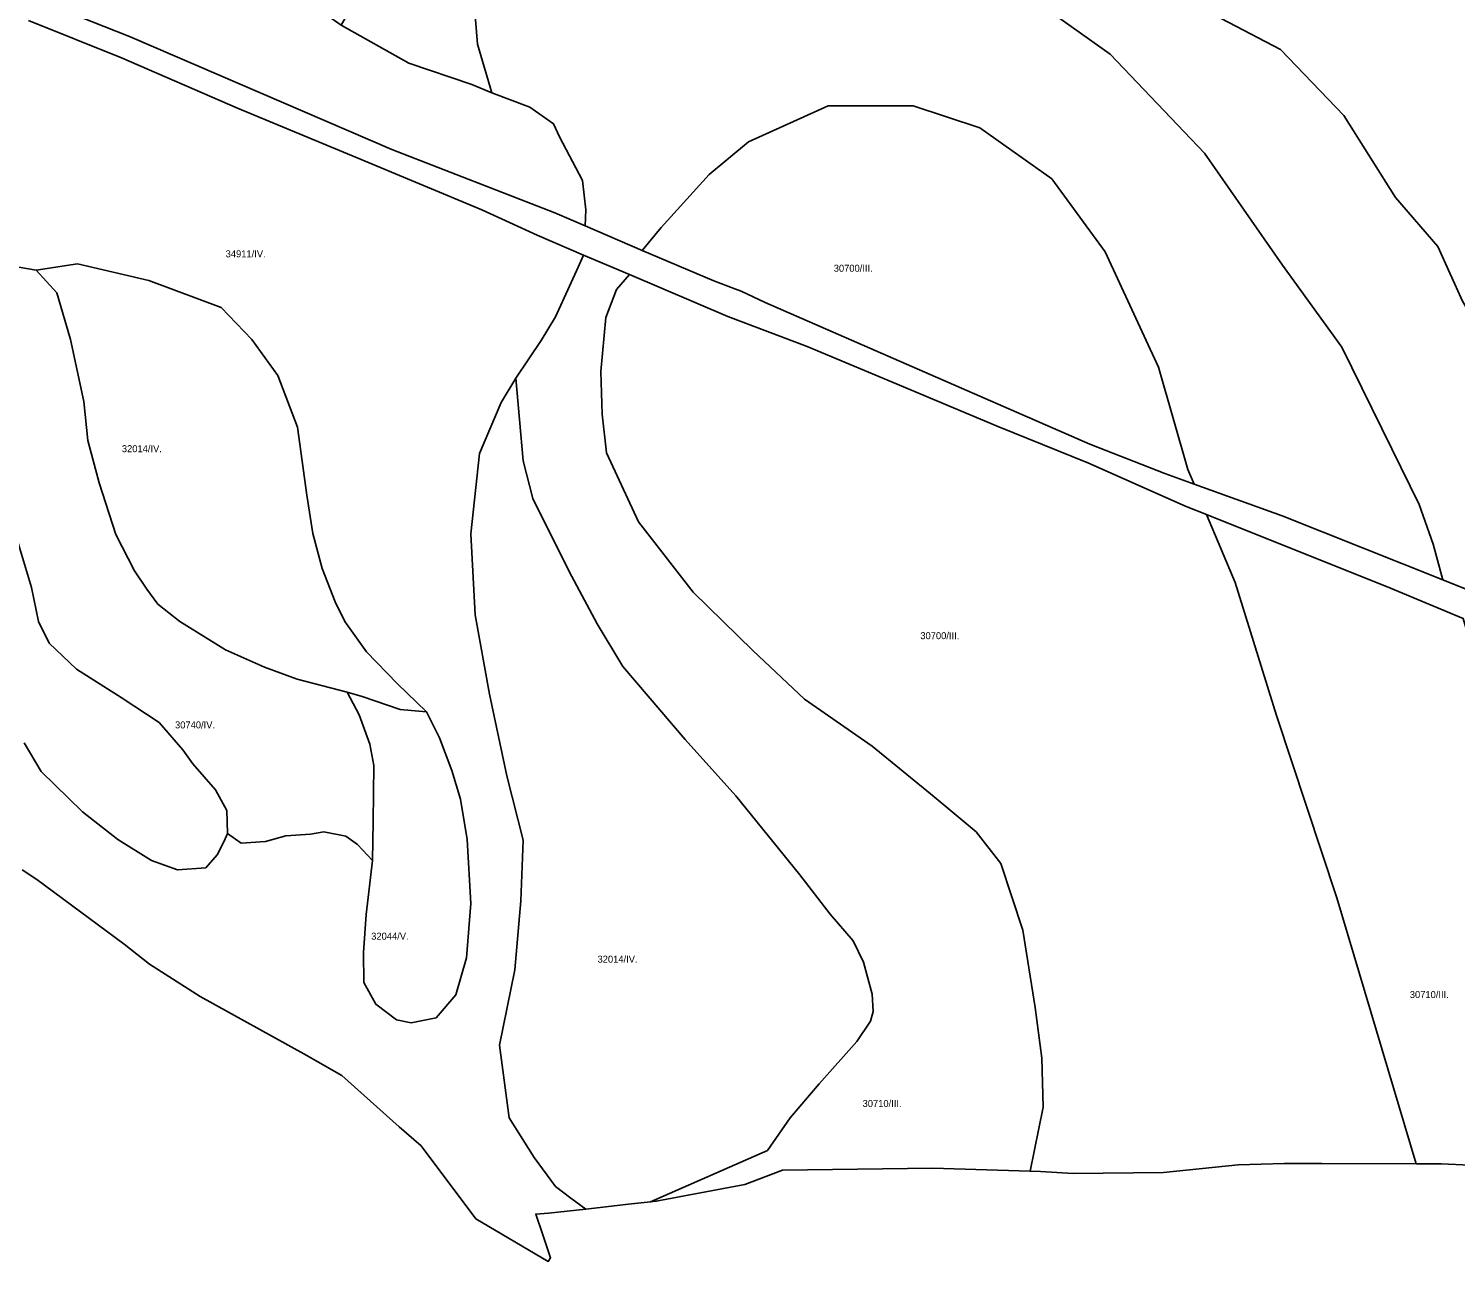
# Model space of a CAD drawing. Extents: x -521621 to -516761, y -1190184 to -1184927.
# Drawn here: x -520002 to -519186, y -1190057 to -1189352 of the extents above; entities that cross this region are included whole.
import ezdxf

# ---------------------------------------------------------------- set-up
doc = ezdxf.new("R2010")
doc.units = 0
doc.layers.add('BPEJ_s', color=7, linetype='Continuous')

msp = doc.modelspace()

# ---------------------------------------------------------------- linework, layer by layer
at = {"layer": 'BPEJ_s'}
for points in [[(-519823.1, -1189350.06), (-519806.14, -1189320.19), (-519800.04, -1189279.46), (-519787.14, -1189225.83), (-519785.79, -1189200.71), (-519787.14, -1189192.56), (-519745.76, -1189203.43), (-519719.98, -1189211.57), (-519700.98, -1189218.36), (-519715.91, -1189225.15), (-519729.48, -1189237.37), (-519742.37, -1189259.77), (-519747.12, -1189293.72), (-519747.79, -1189327.66), (-519745.08, -1189360.92), (-519736.94, -1189388.76), (-519748.47, -1189384), (-519784.43, -1189371.79)], [(-519650.89, -1189478.81), (-519640.16, -1189465.72), (-519612.7, -1189435.46), (-519590.11, -1189416.68), (-519544.58, -1189396.16), (-519495.92, -1189396.16), (-519457.69, -1189408.68), (-519416.67, -1189437.89), (-519386.09, -1189479.63), (-519355.5, -1189545.7), (-519338.82, -1189604.13), (-519335.14, -1189612.54), (-519351.91, -1189606.5), (-519394.82, -1189589.63), (-519580.62, -1189508.74), (-519594.34, -1189502.08), (-519597.85, -1189500.78), (-519609.99, -1189496.28)], [(-519997.55, -1189490.16), (-519973.93, -1189486.62), (-519933.2, -1189496.07), (-519891.87, -1189511.43), (-519874.16, -1189529.74), (-519859.4, -1189550.42), (-519848.18, -1189579.95), (-519842.87, -1189618.94), (-519839.33, -1189640.8), (-519834.02, -1189660.88), (-519826.6, -1189679.9), (-519821.01, -1189691.1), (-519808.57, -1189708.52), (-519791.17, -1189726.56), (-519774.38, -1189742.73), (-519789.3, -1189741.49), (-519811.06, -1189734.02), (-519819.76, -1189731.53), (-519848.36, -1189724.07), (-519867.01, -1189717.23), (-519889.39, -1189707.27), (-519915.5, -1189691.1), (-519927.93, -1189681.15), (-519934.38, -1189672.7), (-519941.46, -1189662.06), (-519952.09, -1189641.39), (-519961.54, -1189611.85), (-519968.03, -1189587.63), (-519970.39, -1189565.19), (-519978.07, -1189529.74), (-519985.74, -1189503.16)], [(-519723.22, -1189551.96), (-519708.63, -1189530.4), (-519700.59, -1189516.75), (-519687.6, -1189488.39), (-519684.5, -1189481.48), (-519658.23, -1189492.66), (-519665.53, -1189501.19), (-519671.78, -1189517.19), (-519674.57, -1189548.14), (-519673.87, -1189572.48), (-519671.44, -1189594.74), (-519653.02, -1189634.04), (-519621.74, -1189674.38), (-519587.67, -1189707.77), (-519558.08, -1189735.65), (-519519.34, -1189762.4), (-519483.87, -1189791.34), (-519459.87, -1189811.54), (-519445.68, -1189829.55), (-519433.13, -1189867.77), (-519426.04, -1189911.99), (-519422.22, -1189940.93), (-519421.46, -1189968.96), (-519429, -1190005.61), (-519484.81, -1190003.91), (-519570.62, -1190005.01), (-519592.2, -1190013.2), (-519642.88, -1190022.74), (-519646.24, -1190023.11), (-519579.27, -1189993.71), (-519566.27, -1189975.04), (-519549.69, -1189955.68), (-519528.13, -1189931.35), (-519520.4, -1189919.74), (-519518.74, -1189914.21), (-519519.29, -1189904.25), (-519524.26, -1189886), (-519530.25, -1189873.77), (-519543.35, -1189858.49), (-519560.81, -1189836.1), (-519597.36, -1189790.79), (-519626.28, -1189758.58), (-519662.05, -1189716.81), (-519676.65, -1189692.47), (-519692.64, -1189662.56), (-519713.49, -1189620.82), (-519719.05, -1189599.26)], [(-519658.23, -1189492.66), (-519601.94, -1189516.62), (-519556.54, -1189533.86), (-519507.3, -1189554.4), (-519447.8, -1189579.47), (-519395.97, -1189600.37), (-519339.66, -1189625.28), (-519328.03, -1189629.94), (-519311.71, -1189668.82), (-519288, -1189744.93), (-519253.62, -1189849.21), (-519208.1, -1190001.4), (-519262.12, -1190001.22), (-519283.62, -1190001.22), (-519309.98, -1190002.04), (-519352.75, -1190006.3), (-519404.45, -1190006.91), (-519423.04, -1190005.79), (-519429, -1190005.61), (-519421.46, -1189968.96), (-519422.22, -1189940.93), (-519426.04, -1189911.99), (-519433.13, -1189867.77), (-519445.68, -1189829.55), (-519459.87, -1189811.54), (-519483.87, -1189791.34), (-519519.34, -1189762.4), (-519558.08, -1189735.65), (-519587.67, -1189707.77), (-519621.74, -1189674.38), (-519653.02, -1189634.04), (-519671.44, -1189594.74), (-519673.87, -1189572.48), (-519674.57, -1189548.14), (-519671.78, -1189517.19), (-519665.53, -1189501.19)], [(-519723.22, -1189551.96), (-519719.05, -1189599.26), (-519713.49, -1189620.82), (-519692.64, -1189662.56), (-519676.65, -1189692.47), (-519662.05, -1189716.81), (-519626.28, -1189758.58), (-519597.36, -1189790.79), (-519560.81, -1189836.1), (-519543.35, -1189858.49), (-519530.25, -1189873.77), (-519524.26, -1189886), (-519519.29, -1189904.25), (-519518.74, -1189914.21), (-519520.4, -1189919.74), (-519528.13, -1189931.35), (-519549.69, -1189955.68), (-519566.27, -1189975.04), (-519579.27, -1189993.71), (-519646.24, -1190023.11), (-519658.79, -1190024.51), (-519683.22, -1190027.22), (-519691.73, -1190020.94), (-519700.58, -1190014.31), (-519712.74, -1189997.72), (-519727.11, -1189975.04), (-519732.63, -1189933.56), (-519723.79, -1189890.43), (-519720.3, -1189850.97), (-519719.05, -1189816.13), (-519728.38, -1189779.43), (-519738.33, -1189732.78), (-519746.41, -1189687.37), (-519748.94, -1189641), (-519744.08, -1189595.09), (-519731.57, -1189565.88)], [(-519208.1, -1190001.4), (-519253.62, -1189849.21), (-519288, -1189744.93), (-519311.71, -1189668.82), (-519328.03, -1189629.94), (-519222.81, -1189672.05), (-519181.35, -1189689.34), (-519166.46, -1189740.01), (-519153.87, -1189796.77), (-519138.14, -1189844.98), (-519114.04, -1189889.74), (-519082.58, -1189926.64), (-519049.15, -1189950.75), (-519010.3, -1189966), (-518966.06, -1189982.72), (-518939.67, -1189985.22), (-518959.14, -1189990.09), (-519013.06, -1189993.13), (-519106.78, -1190001.04), (-519141.44, -1190003.47), (-519150.16, -1190003.47), (-519160.74, -1190002.98), (-519193.76, -1190001.45)], [(-519819.76, -1189731.53), (-519811.06, -1189734.02), (-519789.3, -1189741.49), (-519774.38, -1189742.73), (-519766.92, -1189757.66), (-519759.77, -1189776.32), (-519754.8, -1189792.81), (-519751.07, -1189815.82), (-519748.89, -1189852.52), (-519751.38, -1189883.62), (-519757.6, -1189904.77), (-519768.79, -1189917.84), (-519783.09, -1189920.64), (-519791.48, -1189919.08), (-519803.29, -1189910.06), (-519810.13, -1189897.62), (-519810.44, -1189880.52), (-519808.88, -1189858.74), (-519805.15, -1189827.95), (-519804.84, -1189805.56), (-519804.53, -1189773.52), (-519806.71, -1189761.39), (-519812.93, -1189744.6)]]:
    msp.add_lwpolyline(points, close=True, dxfattribs=at)
for points in [[(-520006.99, -1189287.86), (-519999.5, -1189292.36), (-519964.22, -1189295.07), (-519909.27, -1189314.08), (-519860.42, -1189329.7), (-519832.6, -1189343.27), (-519823.1, -1189350.06), (-519784.43, -1189371.79), (-519748.47, -1189384), (-519736.94, -1189388.76), (-519715.23, -1189396.9), (-519701.66, -1189406.41), (-519698.2, -1189413.9), (-519684.99, -1189438.94), (-519683.25, -1189455.63), (-519683.56, -1189464.86), (-519700.98, -1189457.42), (-519794.24, -1189421.2), (-519944.22, -1189356.48), (-519993.99, -1189336.93), (-520071.75, -1189303.77)], [(-519421.98, -1189339.11), (-519383.19, -1189366.6), (-519329.33, -1189423.2), (-519284.62, -1189487.34), (-519250.68, -1189534.23), (-519222.13, -1189592.45), (-519206.51, -1189624.25), (-519198.41, -1189646.81), (-519192.94, -1189667.39), (-519284.87, -1189630.65), (-519335.14, -1189612.54), (-519338.82, -1189604.13), (-519355.5, -1189545.7), (-519386.09, -1189479.63), (-519416.67, -1189437.89), (-519457.69, -1189408.68), (-519495.92, -1189396.16), (-519544.58, -1189396.16), (-519590.11, -1189416.68), (-519612.7, -1189435.46), (-519640.16, -1189465.72), (-519650.89, -1189478.81), (-519683.56, -1189464.86), (-519683.25, -1189455.63), (-519684.99, -1189438.94), (-519698.2, -1189413.9), (-519701.66, -1189406.41), (-519715.23, -1189396.9), (-519736.94, -1189388.76), (-519745.08, -1189360.92), (-519747.79, -1189327.66)], [(-519993.99, -1189336.93), (-519944.22, -1189356.48), (-519794.24, -1189421.2), (-519700.98, -1189457.42), (-519683.56, -1189464.86), (-519650.89, -1189478.81), (-519609.99, -1189496.28), (-519597.85, -1189500.78), (-519594.34, -1189502.08), (-519580.62, -1189508.74), (-519394.82, -1189589.63), (-519351.91, -1189606.5), (-519335.14, -1189612.54), (-519284.87, -1189630.65), (-519192.94, -1189667.39), (-519099.22, -1189704.82)], [(-519319.63, -1189346.12), (-519285.69, -1189363.91), (-519249.6, -1189401.64), (-519219.98, -1189448.53), (-519195.73, -1189476.56), (-519181.73, -1189507.82), (-519168.26, -1189530.46), (-519155.68, -1189544.18), (-519146.92, -1189554.55), (-519132.97, -1189578.08), (-519121.41, -1189613.17), (-519110.69, -1189651.42), (-519105, -1189691.24), (-519099.22, -1189704.82), (-519192.94, -1189667.39), (-519198.41, -1189646.81), (-519206.51, -1189624.25), (-519222.13, -1189592.45), (-519250.68, -1189534.23), (-519284.62, -1189487.34), (-519329.33, -1189423.2), (-519383.19, -1189366.6), (-519421.98, -1189339.11)], [(-520002.08, -1189347.37), (-519948.89, -1189368.76), (-519882.47, -1189397.47), (-519813.93, -1189425.88), (-519742.72, -1189455.61), (-519710.97, -1189470.22), (-519684.5, -1189481.48), (-519687.6, -1189488.39), (-519700.59, -1189516.75), (-519708.63, -1189530.4), (-519723.22, -1189551.96), (-519731.57, -1189565.88), (-519744.08, -1189595.09), (-519748.94, -1189641), (-519746.41, -1189687.37), (-519738.33, -1189732.78), (-519728.38, -1189779.43), (-519719.05, -1189816.13), (-519720.3, -1189850.97), (-519723.79, -1189890.43), (-519732.63, -1189933.56), (-519727.11, -1189975.04), (-519712.74, -1189997.72), (-519700.58, -1190014.31), (-519691.73, -1190020.94), (-519683.22, -1190027.22), (-519704.62, -1190029.6), (-519711.81, -1190030.12), (-519707.79, -1190042.08), (-519703.36, -1190055.24), (-519704.63, -1190057.23), (-519746.17, -1190032.77), (-519777.43, -1189991.11), (-519790.05, -1189980.14), (-519822.68, -1189950.77), (-519844.43, -1189938.4), (-519903.81, -1189905.61), (-519932.88, -1189887.17), (-519947.25, -1189875.66), (-519997.21, -1189838.78), (-520005.61, -1189833.21)], [(-519181.35, -1189689.34), (-519222.81, -1189672.05), (-519328.03, -1189629.94), (-519339.66, -1189625.28), (-519395.97, -1189600.37), (-519447.8, -1189579.47), (-519507.3, -1189554.4), (-519556.54, -1189533.86), (-519601.94, -1189516.62), (-519658.23, -1189492.66), (-519684.5, -1189481.48), (-519710.97, -1189470.22), (-519742.72, -1189455.61), (-519813.93, -1189425.88), (-519882.47, -1189397.47), (-519948.89, -1189368.76), (-520002.08, -1189347.37)], [(-519181.73, -1189507.82), (-519195.73, -1189476.56), (-519219.98, -1189448.53), (-519249.6, -1189401.64), (-519285.69, -1189363.91), (-519319.63, -1189346.12)], [(-520004.52, -1189760.61), (-519994.76, -1189776.95), (-519971.14, -1189799.96), (-519950.93, -1189815.82), (-519931.66, -1189827.95), (-519916.74, -1189833.24), (-519900.58, -1189832), (-519894.05, -1189824.53), (-519890.01, -1189816.76), (-519888.15, -1189812.4), (-519880.38, -1189818), (-519866.39, -1189817.07), (-519854.89, -1189813.65), (-519840.59, -1189812.71), (-519833.13, -1189811.47), (-519820.39, -1189813.96), (-519813.86, -1189818.62), (-519805.15, -1189827.95), (-519808.88, -1189858.74), (-519810.44, -1189880.52), (-519810.13, -1189897.62), (-519803.29, -1189910.06), (-519791.48, -1189919.08), (-519783.09, -1189920.64), (-519768.79, -1189917.84), (-519757.6, -1189904.77), (-519751.38, -1189883.62), (-519748.89, -1189852.52), (-519751.07, -1189815.82), (-519754.8, -1189792.81), (-519759.77, -1189776.32), (-519766.92, -1189757.66), (-519774.38, -1189742.73), (-519791.17, -1189726.56), (-519808.57, -1189708.52), (-519821.01, -1189691.1), (-519826.6, -1189679.9), (-519834.02, -1189660.88), (-519839.33, -1189640.8), (-519842.87, -1189618.94), (-519848.18, -1189579.95), (-519859.4, -1189550.42), (-519874.16, -1189529.74), (-519891.87, -1189511.43), (-519933.2, -1189496.07), (-519973.93, -1189486.62), (-519997.55, -1189490.16), (-520017.45, -1189486.79)], [(-520017.45, -1189486.79), (-519997.55, -1189490.16), (-519985.74, -1189503.16), (-519978.07, -1189529.74), (-519970.39, -1189565.19), (-519968.03, -1189587.63), (-519961.54, -1189611.85), (-519952.09, -1189641.39), (-519941.46, -1189662.06), (-519934.38, -1189672.7), (-519927.93, -1189681.15), (-519915.5, -1189691.1), (-519889.39, -1189707.27), (-519867.01, -1189717.23), (-519848.36, -1189724.07), (-519819.76, -1189731.53), (-519812.93, -1189744.6), (-519806.71, -1189761.39), (-519804.53, -1189773.52), (-519804.84, -1189805.56), (-519805.15, -1189827.95), (-519813.86, -1189818.62), (-519820.39, -1189813.96), (-519833.13, -1189811.47), (-519840.59, -1189812.71), (-519854.89, -1189813.65), (-519866.39, -1189817.07), (-519880.38, -1189818), (-519888.15, -1189812.4), (-519888.46, -1189799.34), (-519894.99, -1189787.52), (-519908.04, -1189772.59), (-519913.64, -1189764.5), (-519927.31, -1189748.95), (-519949.07, -1189734.64), (-519974.56, -1189718.47), (-519990.1, -1189703.54), (-519996.32, -1189691.1), (-520000.25, -1189671.74), (-520009.4, -1189641.12)], [(-520009.4, -1189641.12), (-520000.25, -1189671.74), (-519996.32, -1189691.1), (-519990.1, -1189703.54), (-519974.56, -1189718.47), (-519949.07, -1189734.64), (-519927.31, -1189748.95), (-519913.64, -1189764.5), (-519908.04, -1189772.59), (-519894.99, -1189787.52), (-519888.46, -1189799.34), (-519888.15, -1189812.4), (-519890.01, -1189816.76), (-519894.05, -1189824.53), (-519900.58, -1189832), (-519916.74, -1189833.24), (-519931.66, -1189827.95), (-519950.93, -1189815.82), (-519971.14, -1189799.96), (-519994.76, -1189776.95), (-520004.52, -1189760.61)]]:
    msp.add_lwpolyline(points, dxfattribs=at)

# ---------------------------------------------------------------- texts
for s, p in [('34911/IV.', (-519889.23, -1189482.79)), ('30700/III.', (-519541.35, -1189491.05)), ('32014/IV.', (-519948.6, -1189594.27)), ('30700/III.', (-519491.8, -1189701.24)), ('30740/IV.', (-519918.19, -1189752.29)), ('32044/V.', (-519805.96, -1189873.15)), ('32014/IV.', (-519676.47, -1189886.29)), ('30710/III.', (-519211.79, -1189906.55)), ('30710/III.', (-519524.83, -1189968.86))]:
    msp.add_text(s, height=4, dxfattribs=at).set_placement(p)

doc.saveas('drawing.dxf')
